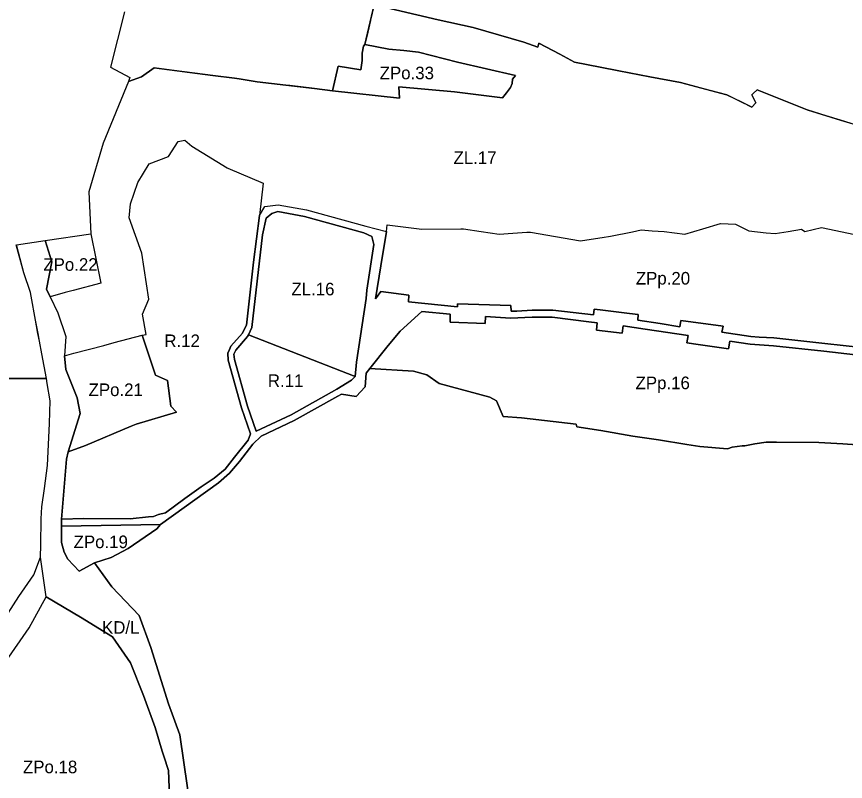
# Model space of a CAD drawing. Extents: x 7418114 to 7422197, y 5546299 to 5548348.
# Drawn here: x 7419162 to 7419820, y 5547046 to 5547653 of the extents above; entities that cross this region are included whole.
import ezdxf

# ---------------------------------------------------------------- set-up
doc = ezdxf.new("R2010")
doc.units = 0
for name, color, linetype in [('_STRZELNICA_SIKORNIK', 7, 'Continuous'), ('linie_rozgraniczajace', 7, 'Continuous'), ('oznaczenia_przeznaczen', 7, 'Continuous')]:
    doc.layers.add(name, color=color, linetype=linetype)

msp = doc.modelspace()

# ---------------------------------------------------------------- linework, layer by layer
at = {"layer": '_STRZELNICA_SIKORNIK'}
msp.add_line((7419251.16, 5547601.44), (7419251.21, 5547601.41), dxfattribs=at)
for points in [[(7419251.21, 5547601.41), (7419261.47, 5547605.03), (7419271.75, 5547612.26), (7419318.13, 5547606.25), (7419335.39, 5547604), (7419339.21, 5547603.55), (7419353.34, 5547601.3), (7419376.07, 5547598.55), (7419398.81, 5547595.8), (7419413.3, 5547594.04), (7419417.68, 5547613.62), (7419435.61, 5547610.71), (7419436.83, 5547618.14), (7419436.66, 5547619.92), (7419436.9, 5547624.01), (7419437.88, 5547629.41), (7419438.88, 5547630.81), (7419446.2, 5547662.24), (7419497.14, 5547650.45), (7419524.91, 5547644.3), (7419565.22, 5547632.57), (7419576.23, 5547628.79), (7419576.93, 5547631.83), (7419593.83, 5547623.22), (7419605.36, 5547616.72), (7419625.72, 5547612.71), (7419640.56, 5547609.89), (7419665.03, 5547605.22), (7419689.5, 5547600.55), (7419726.34, 5547590.87), (7419737.87, 5547585.34), (7419746.25, 5547580.98), (7419749.19, 5547584.53), (7419746.24, 5547590.91), (7419747.19, 5547591.96), (7419750.27, 5547594.84), (7419759.53, 5547591.17), (7419790.14, 5547579.02), (7419816.43, 5547570.76), (7419840.61, 5547563.53)], [(7419248.11, 5547656.83), (7419236.97, 5547612.81), (7419252.42, 5547604.52), (7419251.16, 5547601.44), (7419251.16, 5547601.44)], [(7419092.28, 5547472.79), (7419120.03, 5547480.06), (7419123.81, 5547469.74), (7419127.04, 5547460.01), (7419133.69, 5547441.51), (7419134.96, 5547437.46), (7419137.68, 5547426.33), (7419141.19, 5547412.5), (7419142.59, 5547407.14), (7419145.73, 5547395.09), (7419147.3, 5547389.11), (7419149.94, 5547379.11), (7419153.5, 5547365.76), (7419186.07, 5547365.58), (7419182.45, 5547385.1), (7419180.57, 5547395.24), (7419179.43, 5547401.34), (7419177.49, 5547411.86), (7419173.93, 5547431.07), (7419173.4, 5547434.04), (7419168.26, 5547449.46), (7419162.07, 5547471.66)]]:
    msp.add_lwpolyline(points, dxfattribs=at)
at = {"layer": 'linie_rozgraniczajace'}
for p, q in [((7419438.89, 5547630.81), (7419437.88, 5547629.41)), ((7419457.82, 5547627.14), (7419438.89, 5547630.81)), ((7419438.89, 5547630.81), (7419457.82, 5547627.14)), ((7419469.9, 5547625.98), (7419457.82, 5547627.14)), ((7419457.82, 5547627.14), (7419469.9, 5547625.98)), ((7419512.34, 5547616.81), (7419558.6, 5547606.18)), ((7419640.56, 5547609.89), (7419625.72, 5547612.71)), ((7419558.6, 5547606.18), (7419556.25, 5547603.31)), ((7419261.47, 5547605.03), (7419251.21, 5547601.41)), ((7419554.57, 5547596.65), (7419555.88, 5547599.9)), ((7419555.88, 5547599.9), (7419556.25, 5547603.31)), ((7419556.25, 5547603.31), (7419555.88, 5547599.9)), ((7419413.3, 5547594.04), (7419466.53, 5547588.11)), ((7419466.53, 5547588.11), (7419413.3, 5547594.04)), ((7419548.3, 5547588.46), (7419510.19, 5547593.25)), ((7419283.12, 5547541.94), (7419290.67, 5547553.71)), ((7419290.67, 5547553.71), (7419296.05, 5547554.75)), ((7419358.21, 5547520.67), (7419355.34, 5547494.99)), ((7419251.86, 5547493.12), (7419253, 5547504.32)), ((7419355.34, 5547494.99), (7419359.41, 5547502.28)), ((7419261.74, 5547465.05), (7419251.86, 5547493.12)), ((7419456.09, 5547482.36), (7419456.66, 5547487.78)), ((7419456.66, 5547487.78), (7419484.07, 5547484.19)), ((7419727.26, 5547488.37), (7419733.22, 5547488.07)), ((7419733.22, 5547488.07), (7419743.73, 5547482.99)), ((7419484.07, 5547484.19), (7419515.17, 5547484.47)), ((7419515.17, 5547484.47), (7419517.18, 5547484.46)), ((7419201.1, 5547433.88), (7419189.09, 5547430.56)), ((7419201.62, 5547399.12), (7419200.37, 5547383.71)), ((7419239.91, 5547394.15), (7419262.25, 5547400.04)), ((7419262.25, 5547400.04), (7419265.27, 5547400.62)), ((7419207.82, 5547385.68), (7419231.63, 5547391.97)), ((7419231.63, 5547391.97), (7419239.91, 5547394.15)), ((7419200.37, 5547383.71), (7419207.82, 5547385.68)), ((7419186.07, 5547365.58), (7419153.5, 5547365.76)), ((7419187.06, 5547296.57), (7419188.58, 5547329.87))]:
    msp.add_line(p, q, dxfattribs=at)
for points in [[(7419524.92, 5547644.3), (7419497.14, 5547650.45), (7419446.21, 5547662.24), (7419443.37, 5547650.05), (7419443.32, 5547649.83)], [(7419443.32, 5547649.83), (7419440.68, 5547638.28), (7419438.89, 5547630.81)], [(7419576.23, 5547628.79), (7419565.22, 5547632.57), (7419524.92, 5547644.3)], [(7419437.88, 5547629.41), (7419436.9, 5547624.01), (7419436.66, 5547619.92), (7419436.83, 5547618.14), (7419435.61, 5547610.71), (7419417.68, 5547613.62), (7419413.3, 5547594.04)], [(7419556.25, 5547603.31), (7419558.6, 5547606.18), (7419512.34, 5547616.81), (7419481.47, 5547624.87), (7419469.9, 5547625.98)], [(7419469.9, 5547625.98), (7419481.47, 5547624.87), (7419512.34, 5547616.81)], [(7419625.72, 5547612.71), (7419605.36, 5547616.72), (7419593.83, 5547623.22), (7419576.93, 5547631.83), (7419576.23, 5547628.79)], [(7419318.13, 5547606.25), (7419287.41, 5547610.16), (7419271.75, 5547612.26), (7419261.47, 5547605.03)], [(7419413.3, 5547594.04), (7419398.81, 5547595.8), (7419379.29, 5547598.16), (7419376.07, 5547598.55), (7419353.34, 5547601.3), (7419339.21, 5547603.55), (7419335.39, 5547604), (7419318.13, 5547606.25)], [(7419689.5, 5547600.55), (7419665.03, 5547605.22), (7419640.56, 5547609.89)], [(7419251.15, 5547601.43), (7419231.09, 5547552.49), (7419219.73, 5547513.8), (7419221.3, 5547480.58)], [(7419251.21, 5547601.41), (7419251.15, 5547601.43)], [(7419555.88, 5547599.9), (7419554.57, 5547596.65), (7419551.43, 5547592.55), (7419548.3, 5547588.46)], [(7419746.24, 5547590.91), (7419749.19, 5547584.53), (7419746.25, 5547580.98), (7419736.29, 5547585.92), (7419726.34, 5547590.87), (7419707.92, 5547595.71), (7419689.5, 5547600.55)], [(7419466.53, 5547588.11), (7419465.83, 5547597.15), (7419510.19, 5547593.25), (7419548.3, 5547588.46)], [(7419510.19, 5547593.25), (7419465.83, 5547597.15), (7419466.53, 5547588.11)], [(7419548.3, 5547588.46), (7419551.43, 5547592.55), (7419554.57, 5547596.65)], [(7419790.14, 5547579.02), (7419774.83, 5547585.1), (7419759.53, 5547591.17), (7419750.27, 5547594.84), (7419747.19, 5547591.96), (7419746.24, 5547590.91)], [(7419816.43, 5547570.76), (7419805.09, 5547574.18), (7419790.14, 5547579.02)], [(7419840.61, 5547563.53), (7419828.52, 5547567.15), (7419816.43, 5547570.76)], [(7419296.05, 5547554.75), (7419301.52, 5547550.07), (7419329.5, 5547532.95), (7419330.23, 5547532.65), (7419358.21, 5547520.67)], [(7419253, 5547504.32), (7419258.69, 5547521.18), (7419267.59, 5547536.19), (7419283.12, 5547541.94)], [(7419198.19, 5547248.37), (7419198.1, 5547253.63), (7419198.13, 5547253.97), (7419215.82, 5547254.59), (7419252.6, 5547254.16), (7419267.23, 5547255.73), (7419271.18, 5547256.15), (7419275.01, 5547257.67), (7419280.62, 5547259), (7419296.02, 5547270.45), (7419309.01, 5547279.74), (7419319.42, 5547286.62), (7419327.95, 5547293.63), (7419335.56, 5547303.06), (7419346.32, 5547316.63), (7419348.21, 5547321.65), (7419341, 5547342.4), (7419330.46, 5547380.07), (7419330.15, 5547385.85), (7419331.4, 5547388.66), (7419332.52, 5547391.2), (7419341.75, 5547401.63), (7419342.23, 5547403.02), (7419344.91, 5547408.03), (7419350.58, 5547457.9), (7419355.34, 5547494.99), (7419359.41, 5547502.28), (7419370.02, 5547503.61), (7419392.63, 5547499.46), (7419439.66, 5547486.62), (7419456.09, 5547482.36), (7419451.72, 5547455.04), (7419447.42, 5547428.81), (7419451.63, 5547434.74), (7419473.89, 5547431.93), (7419473.49, 5547426.47), (7419512.47, 5547422.43), (7419512.58, 5547424.91), (7419554.76, 5547423.69), (7419554.95, 5547419.1), (7419559.5, 5547419.14), (7419571.66, 5547420.03), (7419588.27, 5547419.97), (7419620.41, 5547416.32), (7419620.84, 5547420.74), (7419625.6, 5547420.16), (7419648.97, 5547417.33), (7419656.01, 5547416.44), (7419655.56, 5547411.93), (7419673.43, 5547409.18), (7419689, 5547406.79), (7419689.78, 5547411.73), (7419723.25, 5547407.31), (7419722.29, 5547402.44), (7419745.44, 5547399.02), (7419752.07, 5547398.59), (7419763.61, 5547397.84), (7419804.16, 5547393.43), (7419833.13, 5547390.31)], [(7419359.41, 5547502.28), (7419370.02, 5547503.61), (7419392.63, 5547499.46), (7419439.66, 5547486.62), (7419456.09, 5547482.36)], [(7419833.13, 5547390.31), (7419804.16, 5547393.43), (7419763.61, 5547397.84), (7419752.07, 5547398.59), (7419745.44, 5547399.02), (7419722.29, 5547402.44), (7419723.25, 5547407.31), (7419689.78, 5547411.73), (7419689, 5547406.79), (7419673.43, 5547409.18), (7419655.56, 5547411.93), (7419656.01, 5547416.44), (7419648.97, 5547417.33), (7419625.6, 5547420.16), (7419620.84, 5547420.74), (7419620.41, 5547416.32), (7419588.27, 5547419.97), (7419571.66, 5547420.03), (7419559.5, 5547419.14), (7419554.95, 5547419.1), (7419554.76, 5547423.69), (7419512.58, 5547424.91), (7419512.47, 5547422.43), (7419473.49, 5547426.47), (7419473.89, 5547431.93), (7419451.63, 5547434.74), (7419447.42, 5547428.81), (7419451.72, 5547455.04), (7419456.09, 5547482.36), (7419456.66, 5547487.78), (7419484.07, 5547484.19), (7419515.17, 5547484.47), (7419517.18, 5547484.46), (7419531.33, 5547482.34), (7419545.49, 5547480.23), (7419556.47, 5547480.97), (7419567.45, 5547481.72), (7419570.36, 5547481.94), (7419590.22, 5547478.48), (7419610.08, 5547475.02), (7419618.65, 5547476.34), (7419627.22, 5547477.65), (7419633.83, 5547478.74), (7419651.3, 5547482.15), (7419658.14, 5547483.6), (7419666.94, 5547482.92), (7419676.48, 5547482.26), (7419684.71, 5547481.29), (7419692.93, 5547480.32), (7419707.11, 5547484.49), (7419721.3, 5547488.67), (7419727.26, 5547488.37), (7419733.22, 5547488.07), (7419743.73, 5547482.99), (7419757.56, 5547481.41), (7419764.68, 5547480.7), (7419775.06, 5547482.43), (7419785.43, 5547484.16), (7419788.3, 5547482.39), (7419801.45, 5547485.6), (7419854.38, 5547474.48)], [(7419684.71, 5547481.29), (7419692.93, 5547480.32), (7419707.11, 5547484.49), (7419721.3, 5547488.67), (7419727.26, 5547488.37)], [(7419517.18, 5547484.46), (7419531.33, 5547482.34), (7419545.49, 5547480.23), (7419556.47, 5547480.97)], [(7419556.47, 5547480.97), (7419567.45, 5547481.72), (7419570.36, 5547481.94), (7419590.22, 5547478.48), (7419610.08, 5547475.02), (7419618.65, 5547476.34), (7419627.22, 5547477.65)], [(7419627.22, 5547477.65), (7419633.83, 5547478.74), (7419651.3, 5547482.15), (7419658.14, 5547483.6)], [(7419658.14, 5547483.6), (7419666.94, 5547482.92), (7419676.48, 5547482.26), (7419684.71, 5547481.29)], [(7419743.73, 5547482.99), (7419757.56, 5547481.41), (7419764.68, 5547480.7)], [(7419764.68, 5547480.7), (7419775.06, 5547482.43), (7419785.43, 5547484.16), (7419788.3, 5547482.39), (7419801.45, 5547485.6), (7419854.38, 5547474.48)], [(7419284.49, 5547020.27), (7419282.99, 5547054.52), (7419279.31, 5547065.91), (7419278.12, 5547069.72), (7419272.38, 5547088.56), (7419263.1, 5547113.97), (7419252.8, 5547139.9), (7419238.55, 5547160.54), (7419213.15, 5547176.13), (7419185.81, 5547192.23), (7419181.46, 5547223.8), (7419181.65, 5547233.56), (7419182.08, 5547254.34), (7419182.6, 5547263.71), (7419184.61, 5547278.34), (7419187.06, 5547296.57), (7419188.58, 5547329.87), (7419189.13, 5547348.02), (7419186.79, 5547361.66), (7419186.07, 5547365.58), (7419182.45, 5547385.1), (7419180.57, 5547395.24), (7419179.44, 5547401.34), (7419177.49, 5547411.86), (7419173.93, 5547431.07), (7419173.4, 5547434.04), (7419168.26, 5547449.46), (7419162.43, 5547471.73), (7419185.09, 5547475.14), (7419190.46, 5547458.34), (7419186.21, 5547436.62), (7419189.09, 5547430.56), (7419189.09, 5547430.56), (7419189.09, 5547430.56), (7419195.15, 5547417.75), (7419201.62, 5547399.12), (7419200.37, 5547383.71), (7419201.56, 5547372.67), (7419210.48, 5547350.19), (7419212.93, 5547337.8), (7419203.5, 5547307.4), (7419202.16, 5547301.68), (7419198.13, 5547253.97), (7419198.1, 5547253.63), (7419198.19, 5547248.37), (7419198.04, 5547235.39), (7419200.22, 5547227.7), (7419203.1, 5547222.07), (7419212.14, 5547212.63), (7419224.35, 5547219.23), (7419238.05, 5547200.15), (7419259.8, 5547177.58), (7419269.06, 5547152.16), (7419283, 5547107.34), (7419292.16, 5547082.68), (7419300.96, 5547020.44)], [(7419221.3, 5547480.58), (7419229.2, 5547441.34), (7419207.24, 5547435.58), (7419201.1, 5547433.88)], [(7419265.27, 5547400.62), (7419262.38, 5547416.7), (7419267.41, 5547428.68), (7419261.74, 5547465.05)], [(7419189.09, 5547430.56), (7419195.15, 5547417.75), (7419201.62, 5547399.12)], [(7419828.31, 5547384.49), (7419803.23, 5547387.27), (7419763.24, 5547391.66), (7419744.73, 5547392.89), (7419728.57, 5547395.33), (7419727.58, 5547389.28), (7419703.44, 5547392.65), (7419694.64, 5547393.88), (7419695.54, 5547399.78), (7419661.39, 5547404.8), (7419643.94, 5547407.36), (7419643.21, 5547401.68), (7419622.85, 5547404.07), (7419623.45, 5547409.75), (7419616.62, 5547410.62), (7419587.5, 5547414.3), (7419571.75, 5547414.38), (7419554.57, 5547413.42), (7419534.82, 5547414.81), (7419534.39, 5547409.37), (7419506.56, 5547410.3), (7419506.76, 5547416.77), (7419484.28, 5547418.8), (7419467.06, 5547403.24), (7419457.45, 5547391.73), (7419442.86, 5547373.5), (7419439.96, 5547369.87), (7419439.15, 5547358.9), (7419431.9, 5547351.28), (7419420.25, 5547353.22), (7419417.45, 5547351.65), (7419382.81, 5547332.34), (7419356.51, 5547319.8), (7419349.94, 5547313.41), (7419339.4, 5547299.82), (7419331.57, 5547290.44), (7419322.7, 5547282.84), (7419276.72, 5547249.72), (7419198.19, 5547248.37)], [(7419829.64, 5547313.07), (7419818.41, 5547313.8), (7419799.2, 5547314.77), (7419765.84, 5547315.08), (7419757.46, 5547315.04), (7419748.39, 5547313.7), (7419740.65, 5547312.25), (7419738.42, 5547312.07), (7419730.63, 5547311.01), (7419726.8, 5547309.72), (7419704.77, 5547311.53), (7419694.52, 5547313.32), (7419672.16, 5547316.83), (7419651.73, 5547319.82), (7419626.25, 5547324.23), (7419607.21, 5547327.17), (7419606.6, 5547329.42), (7419563.34, 5547334.34), (7419548.63, 5547335.54), (7419543.35, 5547347.79), (7419538.01, 5547350.87), (7419498, 5547361.77), (7419488.09, 5547368.57), (7419477.51, 5547371.59), (7419442.86, 5547373.5), (7419457.45, 5547391.73), (7419467.06, 5547403.24), (7419484.28, 5547418.8), (7419506.76, 5547416.77), (7419506.56, 5547410.3), (7419534.39, 5547409.37), (7419534.82, 5547414.81), (7419554.57, 5547413.42), (7419571.75, 5547414.38), (7419587.5, 5547414.3), (7419616.62, 5547410.62), (7419623.45, 5547409.75), (7419622.85, 5547404.07), (7419643.21, 5547401.68), (7419643.94, 5547407.36), (7419661.39, 5547404.8), (7419695.54, 5547399.78), (7419694.64, 5547393.88), (7419703.44, 5547392.65), (7419727.58, 5547389.28), (7419728.57, 5547395.33), (7419744.73, 5547392.89), (7419763.24, 5547391.66), (7419803.23, 5547387.27), (7419828.31, 5547384.49)], [(7419224.35, 5547219.23), (7419237.41, 5547223.41), (7419251.07, 5547230.72), (7419273.77, 5547246.18), (7419276.72, 5547249.72), (7419322.7, 5547282.84), (7419331.57, 5547290.44), (7419339.4, 5547299.82), (7419349.94, 5547313.41), (7419356.51, 5547319.8), (7419382.81, 5547332.34), (7419417.45, 5547351.65), (7419420.25, 5547353.22), (7419431.9, 5547351.28), (7419439.15, 5547358.9), (7419439.96, 5547369.87), (7419442.86, 5547373.5), (7419477.51, 5547371.59), (7419488.09, 5547368.57), (7419498, 5547361.77), (7419538.01, 5547350.87), (7419543.35, 5547347.79), (7419548.63, 5547335.54), (7419563.34, 5547334.34), (7419606.6, 5547329.42), (7419607.21, 5547327.17), (7419626.25, 5547324.23), (7419651.73, 5547319.82), (7419672.16, 5547316.83), (7419694.52, 5547313.32), (7419704.77, 5547311.53), (7419726.8, 5547309.72), (7419730.63, 5547311.01), (7419738.42, 5547312.07), (7419740.65, 5547312.25), (7419748.39, 5547313.7), (7419757.46, 5547315.04), (7419765.84, 5547315.08), (7419799.2, 5547314.77), (7419818.41, 5547313.8), (7419829.64, 5547313.07)], [(7419188.58, 5547329.87), (7419189.13, 5547348.02), (7419186.79, 5547361.66), (7419186.07, 5547365.58)], [(7419182.08, 5547254.34), (7419182.6, 5547263.71), (7419184.61, 5547278.34), (7419187.06, 5547296.57)], [(7419181.46, 5547223.8), (7419181.65, 5547233.56), (7419182.08, 5547254.34)], [(7419105.33, 5547173.4), (7419112.65, 5547147.49), (7419148.84, 5547169.02), (7419164.09, 5547192.58), (7419176.14, 5547209.85), (7419181.46, 5547223.8)], [(7419292.16, 5547082.68), (7419283, 5547107.34), (7419269.06, 5547152.16), (7419259.8, 5547177.58), (7419238.05, 5547200.15), (7419224.35, 5547219.23)], [(7419300.96, 5547020.44), (7419292.16, 5547082.68)]]:
    msp.add_lwpolyline(points, dxfattribs=at)
for points in [[(7419198.13, 5547253.97), (7419202.16, 5547301.68), (7419203.5, 5547307.4), (7419217.23, 5547312.39), (7419253.39, 5547327.8), (7419257.25, 5547329.39), (7419289.44, 5547339), (7419285, 5547343.63), (7419282.17, 5547364.03), (7419272.69, 5547368.39), (7419262.25, 5547400.04), (7419265.27, 5547400.62), (7419262.38, 5547416.7), (7419267.41, 5547428.68), (7419261.74, 5547465.05), (7419251.86, 5547493.12), (7419253, 5547504.32), (7419258.69, 5547521.18), (7419267.59, 5547536.19), (7419283.12, 5547541.94), (7419290.67, 5547553.71), (7419296.05, 5547554.75), (7419301.52, 5547550.07), (7419329.5, 5547532.95), (7419330.23, 5547532.65), (7419358.21, 5547520.67), (7419355.34, 5547494.99), (7419350.58, 5547457.9), (7419344.91, 5547408.03), (7419342.23, 5547403.02), (7419341.75, 5547401.63), (7419332.52, 5547391.2), (7419331.4, 5547388.66), (7419330.15, 5547385.85), (7419330.46, 5547380.07), (7419341, 5547342.4), (7419348.21, 5547321.65), (7419346.32, 5547316.63), (7419335.56, 5547303.06), (7419327.95, 5547293.63), (7419319.42, 5547286.62), (7419309.01, 5547279.74), (7419296.02, 5547270.45), (7419280.62, 5547259), (7419275.01, 5547257.67), (7419271.18, 5547256.15), (7419267.23, 5547255.73), (7419252.6, 5547254.16), (7419215.82, 5547254.59)], [(7419334.97, 5547384.85), (7419335.42, 5547380.62), (7419345.77, 5547343.79), (7419352.76, 5547323.7), (7419380.48, 5547336.86), (7419416.6, 5547357.22), (7419428.4, 5547364.26), (7419431.22, 5547367.28), (7419432.37, 5547378.61), (7419440.02, 5547429.11), (7419440.53, 5547435.69), (7419446.07, 5547472.07), (7419444.55, 5547478.51), (7419437.98, 5547481.39), (7419390.93, 5547494.27), (7419369.9, 5547498.16), (7419364.97, 5547496.76), (7419360.62, 5547492.99), (7419357.56, 5547479.6), (7419349.31, 5547406.04), (7419346.58, 5547400.42), (7419345.78, 5547398.93), (7419336.49, 5547388.15)], [(7419346.58, 5547400.42), (7419349.31, 5547406.04), (7419357.56, 5547479.6), (7419360.62, 5547492.99), (7419364.97, 5547496.76), (7419369.9, 5547498.16), (7419390.93, 5547494.27), (7419437.98, 5547481.39), (7419444.55, 5547478.51), (7419446.07, 5547472.07), (7419440.53, 5547435.69), (7419440.02, 5547429.11), (7419432.37, 5547378.61), (7419431.22, 5547367.28)], [(7419186.21, 5547436.62), (7419190.46, 5547458.34), (7419185.09, 5547475.14), (7419221.3, 5547480.58), (7419229.2, 5547441.34), (7419207.24, 5547435.58), (7419201.1, 5547433.88), (7419189.09, 5547430.56), (7419189.09, 5547430.56)], [(7419200.37, 5547383.71), (7419207.82, 5547385.68), (7419231.63, 5547391.97), (7419239.91, 5547394.15), (7419262.25, 5547400.04), (7419272.69, 5547368.39), (7419282.17, 5547364.03), (7419285, 5547343.63), (7419289.44, 5547339), (7419257.25, 5547329.39), (7419253.39, 5547327.8), (7419217.23, 5547312.39), (7419203.5, 5547307.4), (7419212.93, 5547337.8), (7419210.48, 5547350.19), (7419201.56, 5547372.67)], [(7419334.97, 5547384.85), (7419336.49, 5547388.15), (7419345.78, 5547398.93), (7419346.58, 5547400.42), (7419431.22, 5547367.28), (7419428.4, 5547364.26), (7419416.6, 5547357.22), (7419380.48, 5547336.86), (7419352.76, 5547323.7), (7419345.77, 5547343.79), (7419335.42, 5547380.62)], [(7419198.04, 5547235.39), (7419198.19, 5547248.37), (7419276.72, 5547249.72), (7419273.77, 5547246.18), (7419251.07, 5547230.72), (7419237.41, 5547223.41), (7419224.35, 5547219.23), (7419212.14, 5547212.63), (7419203.1, 5547222.07), (7419200.22, 5547227.7)], [(7419055.24, 5547099.33), (7419103.29, 5547113.48), (7419153.9, 5547140.97), (7419172.36, 5547167.76), (7419185.81, 5547192.23), (7419213.15, 5547176.13), (7419238.55, 5547160.54), (7419252.8, 5547139.9), (7419263.1, 5547113.97), (7419272.38, 5547088.56), (7419278.12, 5547069.72), (7419279.31, 5547065.91), (7419282.99, 5547054.52), (7419284.49, 5547020.27), (7419283.78, 5546974.77), (7419277.33, 5546943.21), (7419235.6, 5546950.9), (7419203.81, 5546952.4), (7419152.36, 5546955.08), (7419152.36, 5546955.08), (7419157.99, 5546976.72), (7419139.33, 5546992.58), (7419113.59, 5547002.94), (7419101.14, 5547000.37)]]:
    msp.add_lwpolyline(points, close=True, dxfattribs=at)

# ---------------------------------------------------------------- texts
at = {"layer": 'oznaczenia_przeznaczen'}
for s, p in [('ZPo.33', (7419450.67, 5547603.23)), ('ZL.17', (7419509.3, 5547535.99)), ('ZPo.22', (7419183.66, 5547451.15)), ('ZPp.20', (7419654.02, 5547440.23)), ('ZL.16', (7419380.6, 5547431.66)), ('R.12', (7419279.74, 5547390.58)), ('R.11', (7419361.9, 5547358.91)), ('ZPp.16', (7419653.82, 5547357.16)), ('ZPo.21', (7419219.59, 5547351.7)), ('ZPo.19', (7419207.71, 5547230.94)), ('KD/L', (7419230.23, 5547162.98)), ('ZPo.18', (7419167.5, 5547052.23))]:
    msp.add_text(s, height=10, dxfattribs=at).set_placement(p)

doc.saveas('drawing.dxf')
